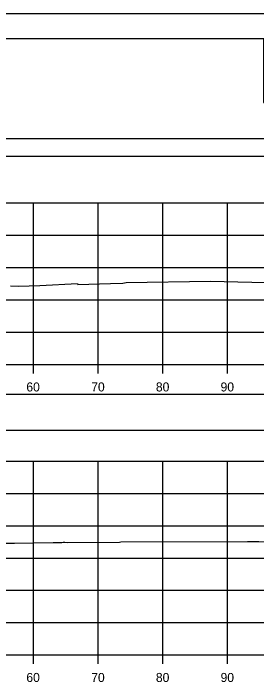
# Model space of a CAD drawing. Extents: x 1369627 to 1374022, y 380035 to 398173.
# Drawn here: x 1372155.4 to 1372193, y 382708.4 to 382812.2 of the extents above; entities that cross this region are included whole.
import ezdxf

# ---------------------------------------------------------------- set-up
doc = ezdxf.new("R2010")
doc.units = 0
for name, color, linetype in [('Default', 7, 'Continuous'), ('R_Axis', 7, 'Continuous'), ('R_Axis Annot', 7, 'Continuous'), ('R_Border', 7, 'Continuous'), ('R_Exist Surface', 7, 'Continuous'), ('R_Grid', 7, 'Continuous'), ('R_No Plot', 7, 'Continuous')]:
    doc.layers.add(name, color=color, linetype=linetype)

msp = doc.modelspace()

# ---------------------------------------------------------------- linework, layer by layer
at = {"layer": 'Default'}
for points in [[(1371948.53, 382790.04), (1372248.53, 382790.04), (1372248.53, 382792.75), (1371948.53, 382792.75)], [(1371948.53, 382747.61), (1372248.53, 382747.61), (1372248.53, 382753.14), (1371948.53, 382753.14)]]:
    msp.add_lwpolyline(points, close=True, dxfattribs=at)
at = {"layer": 'R_Axis'}
for p, q in [((1371948.53, 382757.81), (1372248.53, 382757.81)), ((1372158.53, 382756.41), (1372158.53, 382757.81)), ((1372168.53, 382756.41), (1372168.53, 382757.81)), ((1372178.53, 382756.41), (1372178.53, 382757.81)), ((1372188.53, 382756.41), (1372188.53, 382757.81)), ((1371948.53, 382712.81), (1372248.53, 382712.81)), ((1372158.53, 382711.41), (1372158.53, 382712.81)), ((1372168.53, 382711.41), (1372168.53, 382712.81)), ((1372178.53, 382711.41), (1372178.53, 382712.81)), ((1372188.53, 382711.41), (1372188.53, 382712.81))]:
    msp.add_line(p, q, dxfattribs=at)
at = {"layer": 'R_Border'}
msp.add_line((1371940.53, 382808.27), (1372256.71, 382808.27), dxfattribs=at)
at = {"layer": 'R_Exist Surface'}
for points in [[(1372154.95, 382769.97), (1372156.22, 382769.92), (1372159.48, 382770.02), (1372165.3, 382770.35), (1372165.37, 382770.16), (1372170.41, 382770.34), (1372172.35, 382770.37), (1372172.83, 382770.5), (1372185.87, 382770.67), (1372209.26, 382770.12), (1372217.16, 382770.1), (1372235.41, 382769.76), (1372238.78, 382769.72), (1372239.63, 382769.71), (1372245.06, 382769.62), (1372247.5, 382769.61), (1372248.53, 382769.56)], [(1372151.35, 382730.09), (1372155.55, 382730.1), (1372161.54, 382730.21), (1372162.87, 382730.24), (1372163.11, 382730.25), (1372163.38, 382730.25), (1372163.78, 382730.24), (1372171.81, 382730.27), (1372172, 382730.3), (1372191.59, 382730.36), (1372193.34, 382730.35), (1372195.56, 382730.3), (1372214.94, 382730.26), (1372216.75, 382730.22), (1372229.63, 382729.9), (1372237.27, 382729.86), (1372238.2, 382729.73), (1372241.56, 382729.73), (1372246.69, 382729.82), (1372248.53, 382729.71)]]:
    msp.add_lwpolyline(points, dxfattribs=at)
at = {"layer": 'R_Grid'}
for p, q in [((1371948.53, 382782.81), (1372248.53, 382782.81)), ((1372158.53, 382757.81), (1372158.53, 382782.81)), ((1372168.53, 382757.81), (1372168.53, 382782.81)), ((1372178.53, 382757.81), (1372178.53, 382782.81)), ((1372188.53, 382757.81), (1372188.53, 382782.81)), ((1371948.53, 382777.81), (1372248.53, 382777.81)), ((1371948.53, 382772.81), (1372248.53, 382772.81)), ((1371948.53, 382767.81), (1372248.53, 382767.81)), ((1371948.53, 382762.81), (1372248.53, 382762.81)), ((1371948.53, 382757.81), (1372248.53, 382757.81)), ((1371948.53, 382742.81), (1372248.53, 382742.81)), ((1372158.53, 382712.81), (1372158.53, 382742.81)), ((1372168.53, 382712.81), (1372168.53, 382742.81)), ((1372178.53, 382712.81), (1372178.53, 382742.81)), ((1372188.53, 382712.81), (1372188.53, 382742.81)), ((1371948.53, 382737.81), (1372248.53, 382737.81)), ((1371948.53, 382732.81), (1372248.53, 382732.81)), ((1371948.53, 382727.81), (1372248.53, 382727.81)), ((1371948.53, 382722.81), (1372248.53, 382722.81)), ((1371948.53, 382717.81), (1372248.53, 382717.81)), ((1371948.53, 382712.81), (1372248.53, 382712.81))]:
    msp.add_line(p, q, dxfattribs=at)
at = {"layer": 'R_No Plot'}
msp.add_line((1371928.13, 382812.17), (1372261.46, 382812.17), dxfattribs=at)
for points in [[(1371928.12, 382812.17), (1372261.46, 382812.17), (1372261.46, 382598.83), (1371928.12, 382598.83)], [(1372174.45, 382808.27), (1372194.07, 382808.27), (1372194.07, 382798.39), (1372210.18, 382798.39), (1372233.38, 382798.39), (1372233.38, 382765.72), (1372256.59, 382765.72), (1372256.71, 382602.81), (1371940.53, 382602.81), (1371940.53, 382808.27)]]:
    msp.add_lwpolyline(points, close=True, dxfattribs=at)

# ---------------------------------------------------------------- texts
at = {"layer": 'R_Axis Annot'}
for s, p in [('60', (1372157.41, 382753.61)), ('70', (1372167.44, 382753.61)), ('80', (1372177.44, 382753.61)), ('90', (1372187.44, 382753.61)), ('60', (1372157.41, 382708.61)), ('70', (1372167.44, 382708.61)), ('80', (1372177.44, 382708.61)), ('90', (1372187.44, 382708.61))]:
    msp.add_text(s, height=1.4, dxfattribs=at).set_placement(p)

doc.saveas('drawing.dxf')
